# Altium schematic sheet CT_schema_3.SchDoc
size 461 x 297 mm
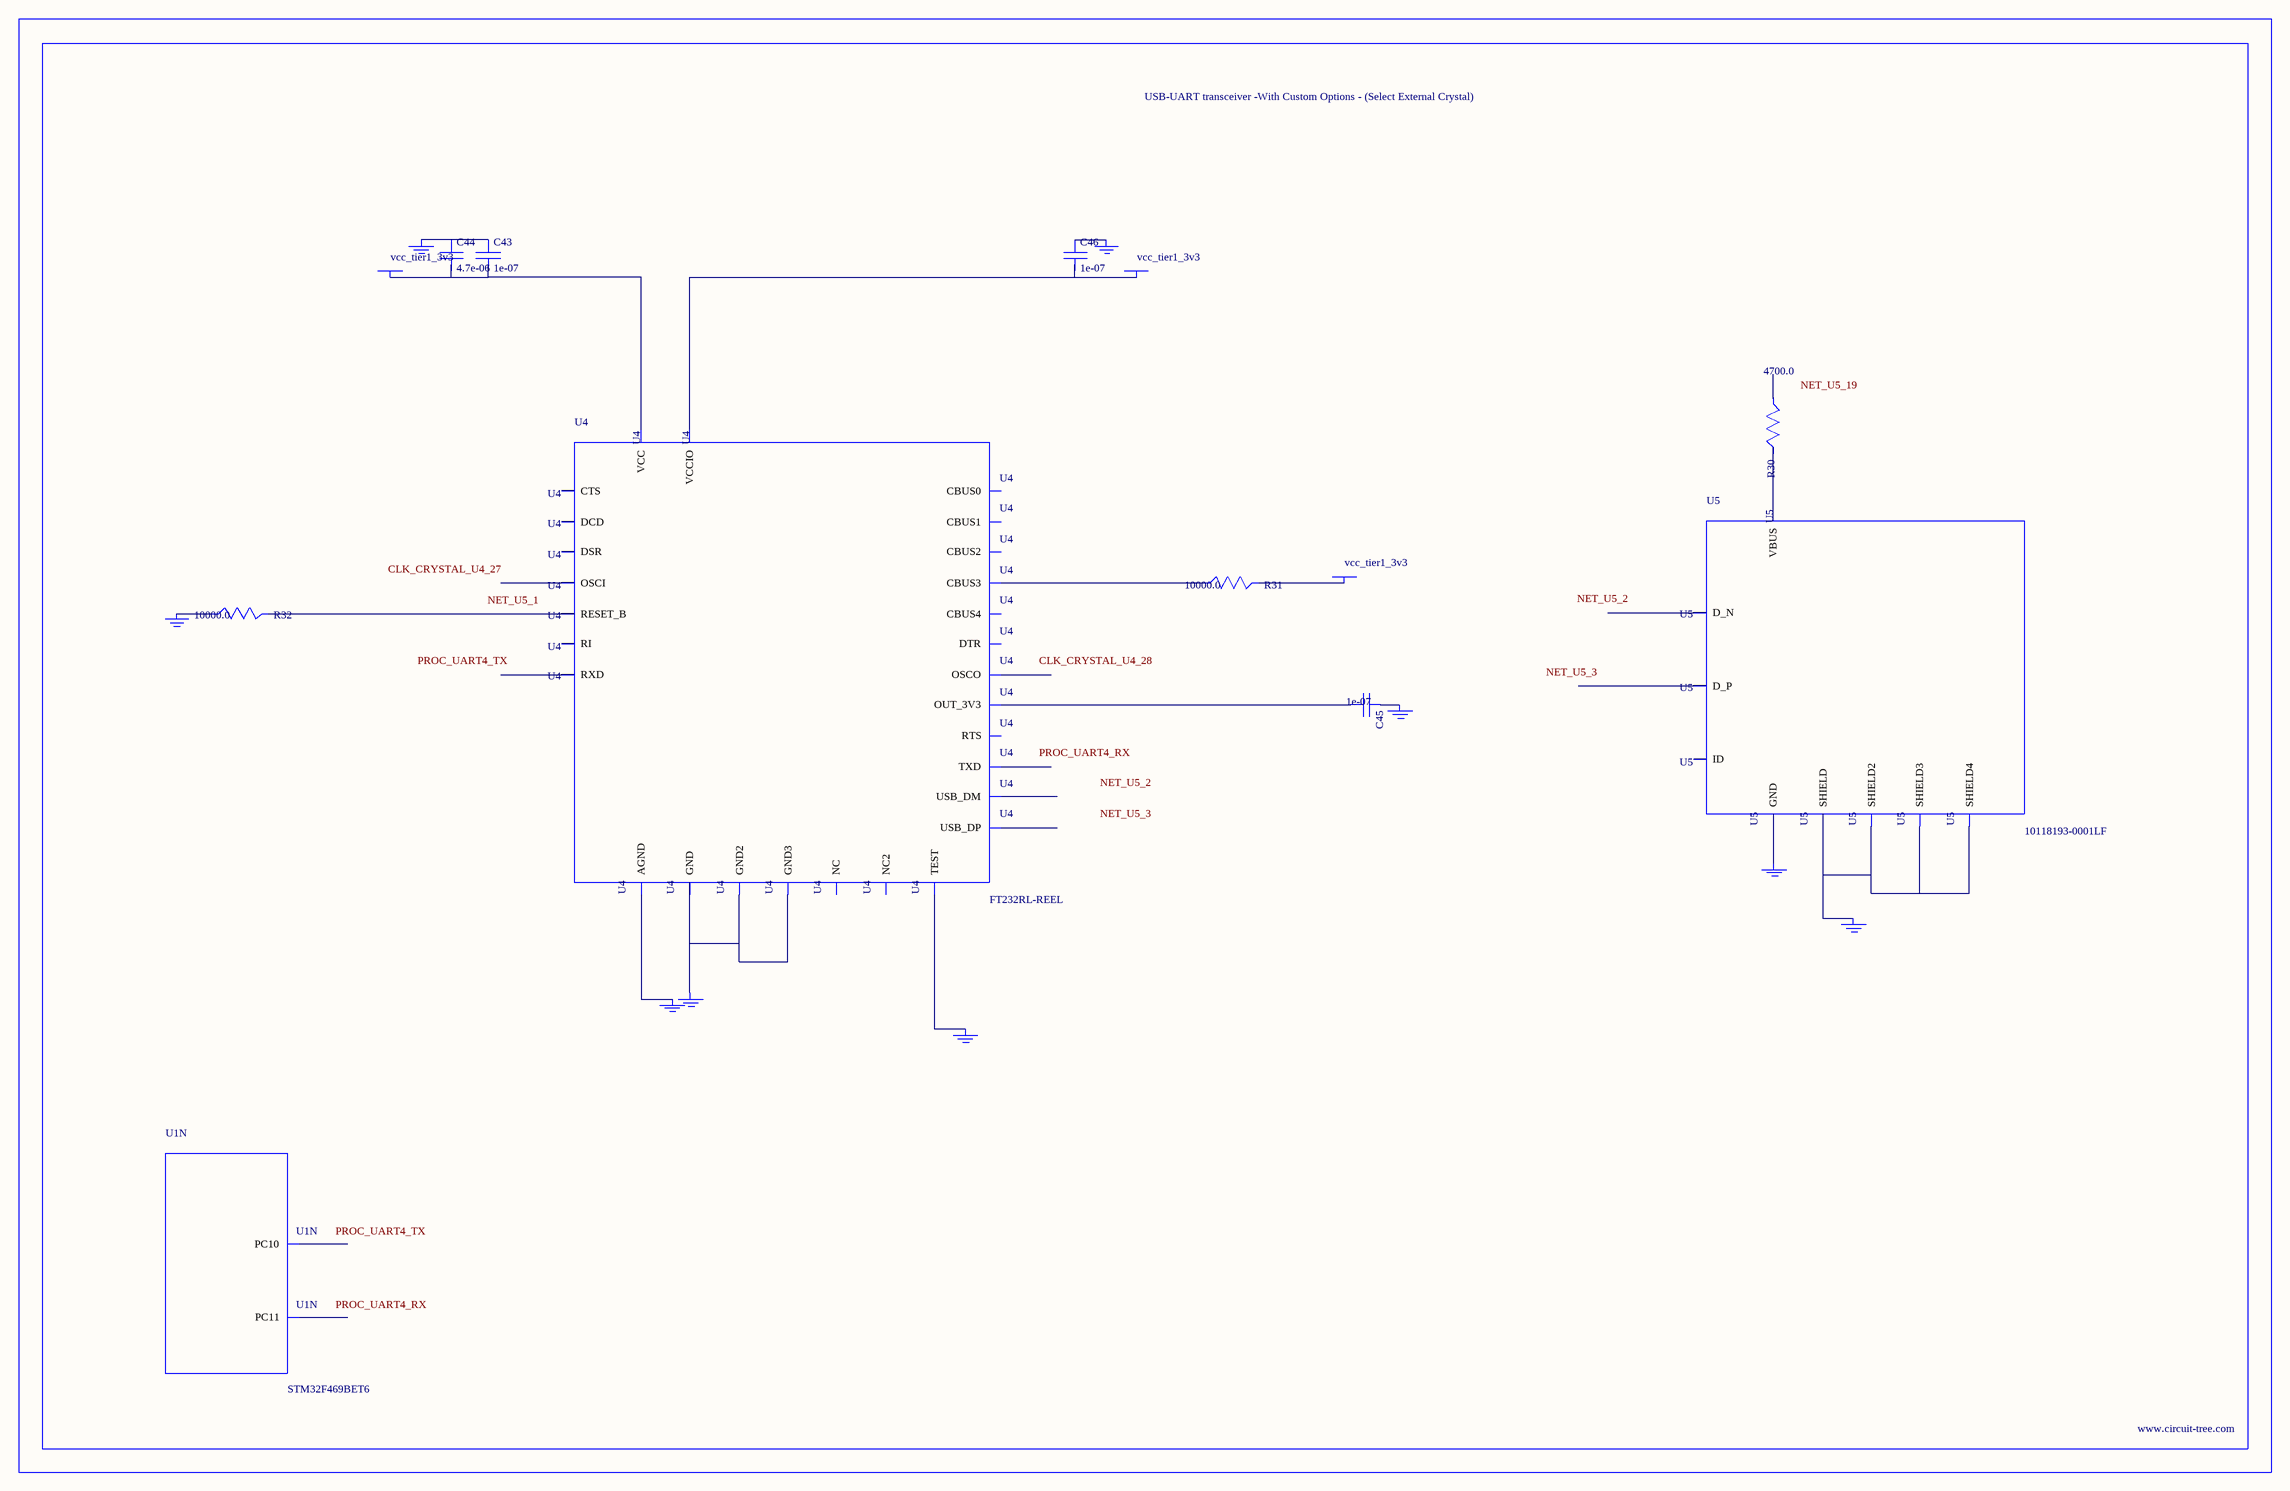
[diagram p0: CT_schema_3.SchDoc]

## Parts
BORDER2  (no value)
C43  1e-07  [C0402]
C44  4.7e-06  [C0805]
C45  1e-07  [C0402]
C46  1e-07  [C0402]
GND_INSTANCE_2_0  (no value)
GND_INSTANCE_2_1  (no value)
GND_INSTANCE_2_2  (no value)
GND_INSTANCE_2_3  (no value)
GND_INSTANCE_2_4  (no value)
GND_INSTANCE_2_5  (no value)
GND_INSTANCE_2_6  (no value)
GND_INSTANCE_2_7  (no value)
GND_INSTANCE_2_8  (no value)
POWER_INSTANCE_2_0  vcc_tier1_3v3
POWER_INSTANCE_2_1  vcc_tier1_3v3
POWER_INSTANCE_2_2  vcc_tier1_3v3
R30  4700.0  [R0603]
R31  10000.0  [R0603]
R32  10000.0  [R0603]
U1  STM32F469BET6  [LQFP208]  (part N of 18)
U4  FT232RL-REEL  [SSOP-28]
U5  10118193-0001LF  [FCI_10118193-0001LF]

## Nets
NetC43_1: C43.1 C44.1 GND_INSTANCE_2_3.0(GND)
NetC43_2: C43.2 C44.2 POWER_INSTANCE_2_2.0(PWR) U4.20(VCC)
NetC45_1: C45.1 GND_INSTANCE_2_1.0(GND)
NetC45_2: C45.2 U4.17(OUT_3V3)
NetC46_1: C46.1 GND_INSTANCE_2_0.0(GND)
NetC46_2: C46.2 POWER_INSTANCE_2_0.0(PWR) U4.4(VCCIO)
NetGND_INSTANCE_2_2_0: GND_INSTANCE_2_2.0(GND) R32.1
NetGND_INSTANCE_2_4_0: GND_INSTANCE_2_4.0(GND) U4.25(AGND)
NetGND_INSTANCE_2_5_0: GND_INSTANCE_2_5.0(GND) U4.26(TEST)
NetGND_INSTANCE_2_6_0: GND_INSTANCE_2_6.0(GND) U4.7(GND) U4.18(GND2) U4.21(GND3)
NetGND_INSTANCE_2_7_0: GND_INSTANCE_2_7.0(GND) U5.6(SHIELD) U5.7(SHIELD2) U5.8(SHIELD3) U5.9(SHIELD4)
NetGND_INSTANCE_2_8_0: GND_INSTANCE_2_8.0(GND) U5.5(GND)
NetPOWER_INSTANCE_2_1_0: POWER_INSTANCE_2_1.0(PWR) R31.2
NetR30_2: R30.2 U5.1(VBUS)
NetR31_1: R31.1 U4.14(CBUS3)
NetR32_2: R32.2 U4.19(RESET_B)

Not connected (* = marked no-connect by the designer): R30 1; U1 161(PC10) 162(PC11); U4 1(TXD) 2(DTR) 3(RTS) 5(RXD) 6(RI) 8(NC) 9(DSR) 10(DCD) 11(CTS) 12(CBUS4) 13(CBUS2) 15(USB_DP) 16(USB_DM) 22(CBUS1) 23(CBUS0) 24(NC2) 27(OSCI) 28(OSCO); U5 2(D_N) 3(D_P) 4(ID)

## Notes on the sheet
- Labels drawn without touching a wire or pin: CLK_CRYSTAL_U4_27, CLK_CRYSTAL_U4_28, NET_U5_1, NET_U5_2, NET_U5_3, NET_U5_19, PROC_UART4_RX, PROC_UART4_TX

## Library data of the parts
BORDER2 = BORDER_PAGE2
C43 C45 C46 = C0402C104K3RACTU
C44 = C0805C475K4RACTU
GND_INSTANCE_2_0-GND_INSTANCE_2_8 = GND
POWER_INSTANCE_2_0-POWER_INSTANCE_2_2 = PWR
R30 = RC0603JR-074K7L
R31 R32 = RC0603JR-0710KL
